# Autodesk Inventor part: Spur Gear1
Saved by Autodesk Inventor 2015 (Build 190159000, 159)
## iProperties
Created: 2014-06
Part Number: Spur Gear1
Material: Steel
Document SubType Name: Modeling
Designer: User
Categories: <?xml version="1.0" encoding="UTF-16"?> <MemberInstance><Categories><FamilyTemplate><FamilyTemplateParameter ValueType="xs:double" Id="1" ObjectReferenceKey="da
Density: 1 g/cm^3
Appearance: Steel
CustomPartVersion: 1
Author: User
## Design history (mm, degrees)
sketch "Sketch1"
  geometry: C1 r 10.2 at (0, 0)
  constraints: 1 centre point
  dimensions: "d0" = 20.4 diameter of C1 (= da_da)
extrude "Extrusion1" new body sketch "Sketch1" distance "d1" = 4 (= da_b); taper "d2" = 0 deg
workplane "Work Plane2"
sketch "Sketch2"
  geometry: C1 r 10.2 at (0, 0) reference; C2 r 9.4 at (0, 0)
  constraints: 1 centre point, 1 coincident
  dimensions: "d3" = 18.8 diameter of C2 (= da_dw)
feature "Pitch Diameter" sketch "Sketch2" dims "d4" = 10, "d5" = 0
workplane "Work Plane8"
workplane "Work Plane9"
feature "Spur Gear" dims "da_b" = 4, "da_d" = 18.79786, "da_aw" = 18.8, "da_da" = 20.4, "da_df" = 16.8, "da_dw" = 18.8, angle "da_beta" = 40 deg, "da_lefttooth" = 10, "da_righttooth" = 0
body "Solid1"
body "Srf1"
other parameters: "d16" = 18.8 (= da_aw), "d17" = 0, "d34" = 10 deg (computed from da_z), "d39" = 0, "d41" = 0, "d43" = 18.8 (= da_aw), "d46" = 18.8 (= da_aw), "d47" = 0, "d48" = 0
